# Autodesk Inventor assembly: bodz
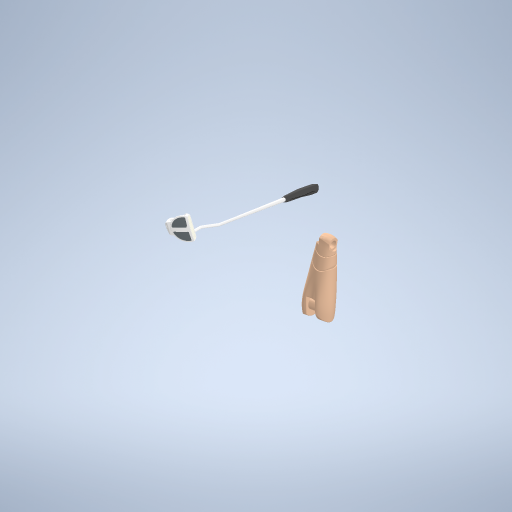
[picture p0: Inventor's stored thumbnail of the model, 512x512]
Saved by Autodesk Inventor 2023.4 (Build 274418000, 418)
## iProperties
Created: 2019-07
Part Number: bodz
Material: Všeobecné
Document SubType Name: Modeling
Designer: bruno
Density: 1 g/cm^3
Appearance: Par défaut
Title: C:\Users\Kuba\Desktop\inventory\golfclub.stp
Author: Kuba
Sending System: Autodesk Inventor 2019
Preprocessor: ST-DEVELOPER v17
Created: 2019-10
Part Number: Hand Full-golf
Document SubType Name: Assembly
Designer: yello
Author: yello
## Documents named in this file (6)
- **C:\Users\bruno\Documents\1-Cours-2025-26\1STI2D\ETLV\Diversité et inclusion\Hand Full-golf.iam*LocalDocs*xAaaaauaaAaaaaaaaAaaaqwx1Tb*golfclub.ipt
- C:\Users\bruno\Documents\1-Cours-2025-26\1STI2D\ETLV\Diversité et inclusion\Hand Full-golf.iam
- C:\Users\bruno\Documents\1-Cours-2025-26\1STI2D\ETLV\Diversité et inclusion\Prototype 2 (Realistic Hand)\Wrist Rotation.ipt
- C:\Users\bruno\Documents\1-Cours-2025-26\1STI2D\ETLV\Diversité et inclusion\Prototype 2 (Realistic Hand)\Arm to Wrist Connection.ipt
- C:\Users\bruno\Documents\1-Cours-2025-26\1STI2D\ETLV\Diversité et inclusion\Prototype 2 (Realistic Hand)\Arm.ipt
- C:\Users\bruno\Documents\1-Cours-2025-26\1STI2D\ETLV\Diversité et inclusion\Tools\golfclub.stp
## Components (4 placed, 4 different names)
1. Wrist Rotation:1 — Mate:1, Mate:2, Mate:4
2. Arm to Wrist Connection:1 — Mate:1, Mate:2, Mate:3
3. Arm:1 — Mate:3, Mate:4
4. golfclub:1
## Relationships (4: Mate 4)
- Mate:1: Wrist Rotation:1 ↔ Arm to Wrist Connection:1
- Mate:2: Wrist Rotation:1 ↔ Arm to Wrist Connection:1
- Mate:3: Arm to Wrist Connection:1 ↔ Arm:1
- Mate:4: Wrist Rotation:1 ↔ Arm:1
